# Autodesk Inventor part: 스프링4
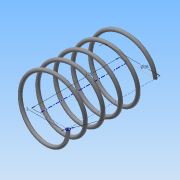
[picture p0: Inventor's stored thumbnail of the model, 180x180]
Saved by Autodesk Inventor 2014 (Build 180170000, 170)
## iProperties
Created: 2015-06
Part Number: 스프링4
Material: 강철, 연강
Document SubType Name: Modeling
Designer: MYHOME
Density: 7.86 g/cm^3
Appearance: 강철
Mass: 1.52988 g
Surface Area: 7.87024 cm^2
Volume: 0.194641 cm^3
Author: MYHOME
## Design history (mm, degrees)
sketch "스케치1"
  geometry: L1 (0, 0)-(8, 0); L2 (8, 0)-(8, 14.5); L3 (8, 14.5)-(0, 14.5); L4 (0, 14.5)-(0, 0); C1 r 0.5 at (8, 0)
  constraints: 8 end point, 2 parallel, 1 centre point, 1 coincident, 1 horizontal, 1 perpendicular
  dimensions: "d0" = 1 diameter of C1; "d1" = 16 diameter of L2 L4; "d2" = 14.5 distance of L3.end L1.start (derived)
feature "코일1" pitch "d3" = 10; turns "d5" = 5; dims "d4" = 14.5 (= d2), "d6" = 0, angle "d7" = 90 deg, angle "d8" = 90 deg, "d9" = 0, "d10" = 0
sketch "스케치2"
  geometry: L1 (-8.5, 0)-(-7.5, 0) reference; 1 further point
  constraints: 1 horizontal alignment
extrude "돌출1" cut sketch "스케치2" distance "d11" = 10; taper "d12" = 0 deg
node "작업 평면1"
sketch "스케치3"
  geometry: L1 (-7.5, 0)-(-8.5, 0) reference; 1 further point
  constraints: 1 horizontal alignment
extrude "돌출2" cut sketch "스케치3" distance "d14" = 10; taper "d15" = 0 deg
node "솔리드1"
node "절단 모서리 투영1"
node "절단 모서리 투영2"
other parameters: "d13" = 14.5 (= d2)
